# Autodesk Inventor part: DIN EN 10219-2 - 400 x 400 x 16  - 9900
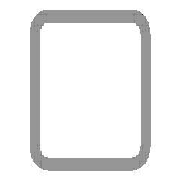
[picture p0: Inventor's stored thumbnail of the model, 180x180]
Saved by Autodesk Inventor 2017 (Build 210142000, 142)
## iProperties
IsCustomPart: 1
Created: 2017-11
Part Number: DIN EN 10219-2 - 400 x 400 x 16  - 9900
Material: Steel, Mild
Description: Cold formed welded structural hollow sections of non-alloy and fine grain structural steel
Document SubType Name: Modeling
Standard: DIN
Designer: iusti
Standard Revision: 2006-07
Standards Organization: DIN
Language: en-US
Size Designation: 400 x 400 x 16
Categories: <MemberInstance><Categories><Category DisplayName="Structural Shapes" InternalName="089c4875-fa83-4c05-b084-43b9cc11f5ed" Mnemonic="GRDR"><CategoryParameter Dis
Stock Number: 400 x 400 x 16
Density: 7.85 g/cm^3
Appearance: Semi-Polished
Mass: 1.76924e+06 g
Surface Area: 282196 cm^2
Volume: 225381 cm^3
_CCFamilyMember: 142
_CCFamilyDisplayName: DIN EN 10219-2 (Square Hollow Section - Cold Formed) - Cold formed welded structural hollow sections of non-alloy and fine grain structural steel
_FrameMemberDoc: Frame Member File
_Version: 15.0.0
_GetPNFromCC: 1
G_L: 9900.000 mm
G_W: 400.000 mm
G_H: 400.000 mm
+A69F4663-CFB7-4D18-824B-3D97B0B5E8F0+CUTDETAIL1: Cut
+26595D0A-3E89-4A2F-9DA7-6BDC5E0BE6FD+CUTDETAIL2: Cut
Author: iusti
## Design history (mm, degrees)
node "Start plane"
node "End plane"
sketch "Sketch"
  geometry: L1 (-200, -152)-(-200, 152); L2 (-152, 200)-(152, 200); L3 (200, 152)-(200, -152); L4 (152, -200)-(-152, -200); L5 (-152, 184)-(152, 184); L6 (184, 152)-(184, -152); L7 (152, -184)-(-152, -184); L8 (-184, -152)-(-184, 152); L9 (0, 293.918)-(0, -293.918) reference; L10 (-293.918, 0)-(293.918, 0) reference; A1 r 48 centre (-152, -152) between (-200, -152) and (-152, -200); A2 r 48 centre (-152, 152) between (-152, 200) and (-200, 152); A3 r 48 centre (152, 152) between (200, 152) and (152, 200); A4 r 48 centre (152, -152) between (152, -200) and (200, -152); A5 r 32 centre (-152, 152) between (-152, 184) and (-184, 152); A6 r 32 centre (152, 152) between (184, 152) and (152, 184); A7 r 32 centre (152, -152) between (152, -184) and (184, -152); A8 r 32 centre (-152, -152) between (-184, -152) and (-152, -184)
  constraints: 16 end point, 16 point on circle, 8 centre point, 8 tangent, 4 parallel, 3 equal radius, 2 perpendicular, 7 other
  dimensions: "d7" = 48 radius of A1 (= G_IR); "d10" = 400 distance between parallel lines of L2 L4 (= G_H); "d11" = 400 distance between parallel lines of L1 L3 (= G_W); "d12" = 16 distance between parallel lines of L3 L6 (= G_T); "d15" = 200 distance between parallel lines of L2 L10 (= 0.5 x d10); "d16" = 200 distance between parallel lines of L9 L3 (= 0.5 x d11)
extrude "Body" new body sketch "Sketch" stored distance "d3" = 9900 (= G_L); taper "d4" = 0 deg
node "Driven Length"
  sketch "Sketch3"
    geometry: L1 (0, 0)-(10, 0) reference
    constraints: 2 end point, 1 horizontal
  workplane "Work Plane3"
  sketch "Sketch4"
    geometry: L1 (-2, -200)-(12, -200) reference; L2 (-2, 9700)-(12, 9700) reference
    dimensions: "d18" = 9900 distance between parallel lines of L1 L2 (derived)
workplane "Work Plane4"
split "Split1"
workplane "Work Plane5"
split "Split2"
body "Solid1"
other parameters: "G_W" = 400 [user parameter; used in 1 equation term], "G_H" = 400 [user parameter; used in 1 equation term], "G_T" = 16 [user parameter; used in 1 equation term], "G_IR" = 48 [user parameter; used in 1 equation term], "G_L" = 9900 (= d18) [user parameter; used in 1 equation term], "d17" = 90 deg
